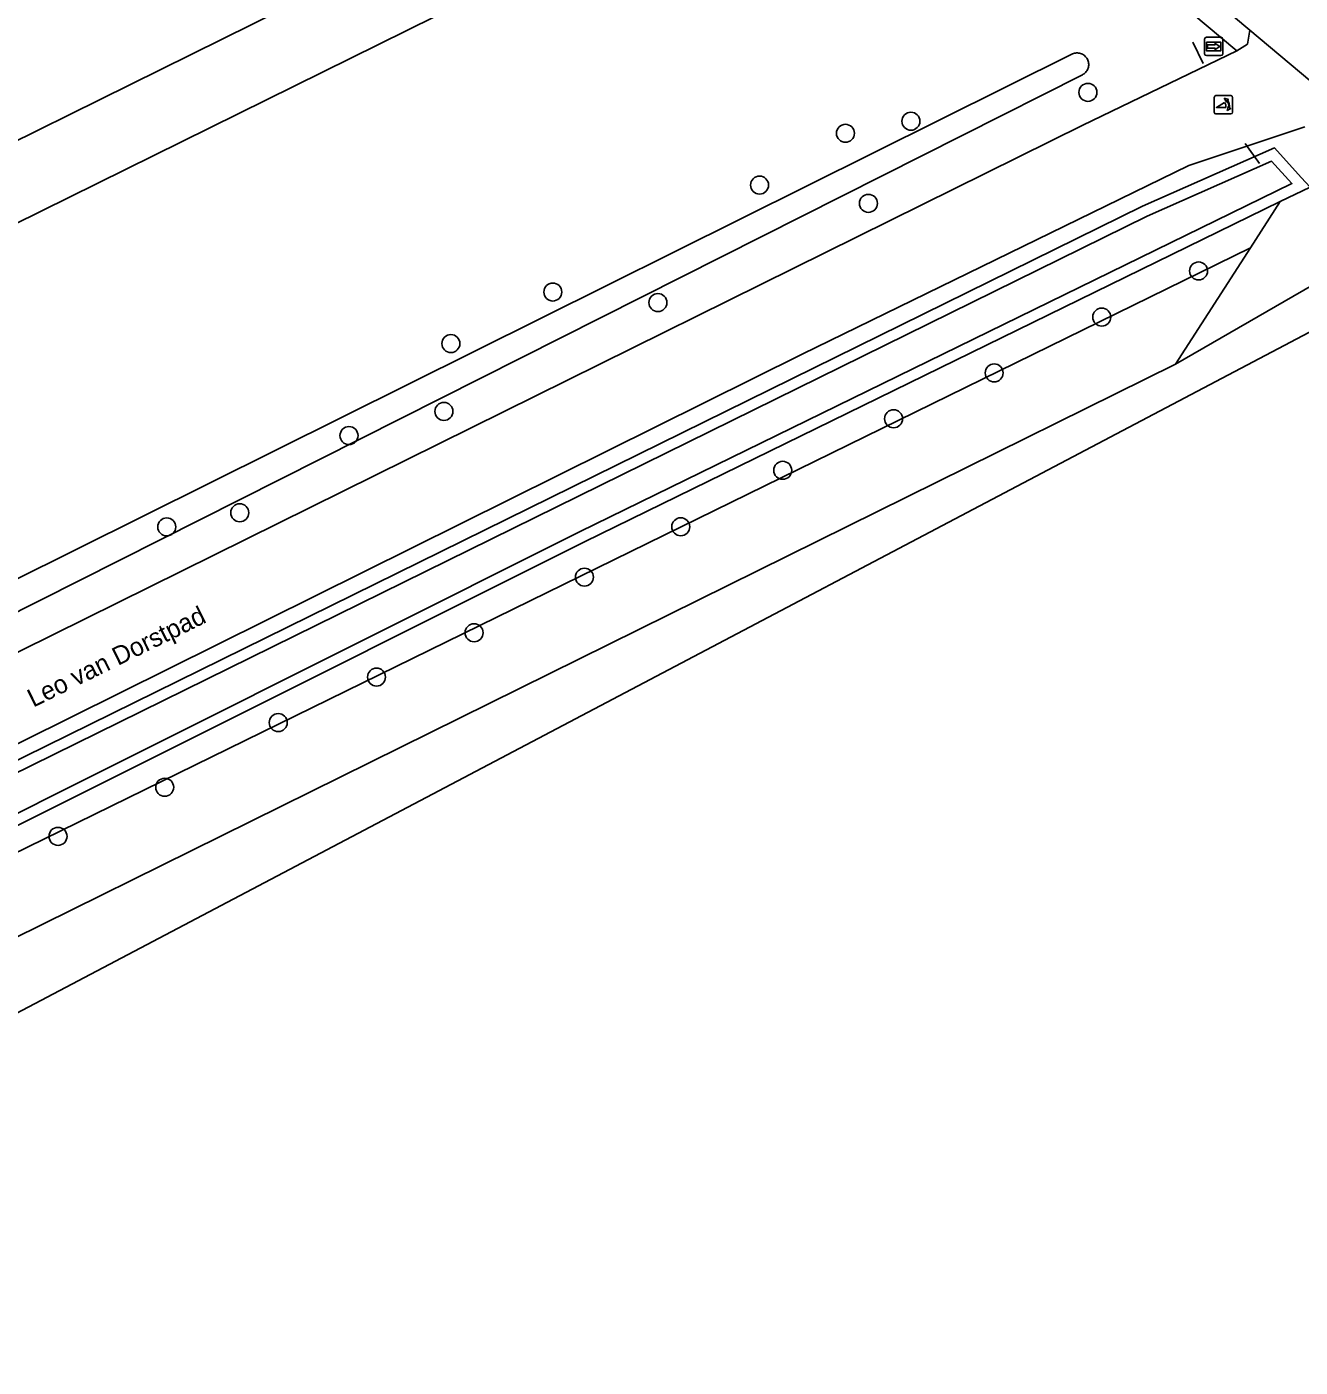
# Model space of a CAD drawing. Extents: x 157321 to 158827, y 386650 to 388532.
# Drawn here: x 158230.9 to 158300.1, y 386849.9 to 386922.7 of the extents above; entities that cross this region are included whole.
import ezdxf

# ---------------------------------------------------------------- set-up
doc = ezdxf.new("R2010")
doc.units = 0
for name, color, linetype in [('IMGEO_Boom', 7, 'Continuous'), ('IMGEO_Fietspad_gesloten', 7, 'Continuous'), ('IMGEO_Grasland_overig', 7, 'Continuous'), ('IMGEO_Groenvoorziening', 7, 'Continuous'), ('IMGEO_Hek', 7, 'Continuous'), ('IMGEO_Openbare_ruimte_label', 7, 'Continuous'), ('IMGEO_Poller', 7, 'Continuous'), ('IMGEO_Voetpad_open', 7, 'Continuous'), ('IMGEO_Waterloop', 7, 'Continuous'), ('IMGEO_Wegwijzer', 7, 'Continuous')]:
    doc.layers.add(name, color=color, linetype=linetype)

msp = doc.modelspace()

# ---------------------------------------------------------------- linework, layer by layer
at = {"layer": 'IMGEO_Boom'}
for centre in [(158288.578, 386919.112), (158278.966, 386917.546), (158275.41, 386916.888), (158270.741, 386914.074), (158276.654, 386913.082), (158294.588, 386909.409), (158259.514, 386908.266), (158265.22, 386907.691), (158289.327, 386906.901), (158253.976, 386905.464), (158283.486, 386903.868), (158253.6, 386901.778), (158278.021, 386901.378), (158248.443, 386900.465), (158272, 386898.579), (158242.51, 386896.275), (158238.542, 386895.506), (158266.464, 386895.51), (158261.23, 386892.774), (158255.237, 386889.752), (158249.937, 386887.346), (158244.599, 386884.876), (158238.432, 386881.358), (158232.638, 386878.693)]:
    msp.add_circle(centre, 0.489, dxfattribs=at)
at = {"layer": 'IMGEO_Fietspad_gesloten'}
for points in [[(158278.393, 386938.472), (158282.172, 386935.247), (158297.373, 386922.485)], [(158296.67, 386921.366), (158297.251, 386921.735), (158297.373, 386922.485)], [(158297.373, 386922.485), (158304.001, 386916.938)], [(158157.22, 386852.456), (158288.293, 386917.324), (158296.67, 386921.366)], [(158300.362, 386917.233), (158294.063, 386915.13), (158273.057, 386904.892), (158206.905, 386872.045), (158161.028, 386849.47)]]:
    msp.add_lwpolyline(points, dxfattribs=at)
at = {"layer": 'IMGEO_Grasland_overig'}
for points in [[(158303.723, 386910.343), (158293.34, 386904.342)], [(158305.326, 386908.574), (158181.714, 386843.44)], [(158178.328, 386847.485), (158293.34, 386904.342)]]:
    msp.add_lwpolyline(points, dxfattribs=at)
at = {"layer": 'IMGEO_Groenvoorziening'}
for points in [[(158143.449, 386873.515), (158167.832, 386885.54), (158167.852, 386885.55), (158190.13, 386896.57), (158190.213, 386896.611), (158274.656, 386938.392), (158275.715, 386938.916)], [(158149.876, 386872.225), (158169.601, 386881.953), (158176.662, 386887.485), (158183.352, 386890.976), (158188.821, 386892.547), (158191.985, 386893.025), (158279.098, 386936.083)], [(158161.727, 386849.006), (158291.549, 386912.934), (158298.705, 386916.096), (158300.167, 386914.49)], [(158300.167, 386914.49), (158300.642, 386913.968), (158299.023, 386913.177)], [(158299.023, 386913.177), (158261.233, 386894.691), (158214.135, 386871.125), (158171.324, 386850.102), (158176.019, 386846.697), (158176.491, 386846.372), (158176.951, 386845.957), (158177.352, 386845.485), (158177.649, 386845.026), (158189.15, 386830.884), (158211.608, 386806.05), (158208.447, 386803.533)], [(158297.408, 386910.666), (158299.023, 386913.177)], [(158297.408, 386910.666), (158175.433, 386850.883), (158178.328, 386847.485)], [(158293.34, 386904.342), (158297.408, 386910.666)]]:
    msp.add_lwpolyline(points, dxfattribs=at)
at = {"layer": 'IMGEO_Hek'}
for points in [[(158294.272, 386921.841), (158294.837, 386920.678)], [(158297.904, 386915.252), (158297.343, 386916.017), (158297.115, 386916.329)]]:
    msp.add_lwpolyline(points, dxfattribs=at)
at = {"layer": 'IMGEO_Poller'}
for p, q in [((158295.438, 386918.839), (158295.438, 386918.032)), ((158295.438, 386918.839), (158295.438, 386918.032)), ((158296.34, 386918.934), (158295.532, 386918.934)), ((158296.34, 386918.934), (158295.532, 386918.934)), ((158296.434, 386918.032), (158296.434, 386918.839)), ((158296.434, 386918.032), (158296.434, 386918.839)), ((158295.532, 386917.937), (158296.34, 386917.937)), ((158295.532, 386917.937), (158296.34, 386917.937))]:
    msp.add_line(p, q, dxfattribs=at)
for points in [[(158296.073, 386918.29), (158295.56, 386918.29), (158295.99, 386918.565)], [(158296.117, 386918.663), (158296.105, 386918.59), (158295.98, 386918.795)], [(158295.98, 386918.795), (158296.211, 386918.729), (158296.14, 386918.697)], [(158296.133, 386918.118), (158296.199, 386918.349), (158296.229, 386918.281)], [(158296.265, 386918.254), (158296.337, 386918.243), (158296.133, 386918.118)]]:
    msp.add_lwpolyline(points, dxfattribs=at)
for centre, radius, start, end in [((158295.532, 386918.839), 0.0946, 90, 180), ((158295.532, 386918.839), 0.0946, 90, 180), ((158295.745, 386918.34), 0.332, 351.32473, 42.4854), ((158295.759, 386918.35), 0.476, 351.75274, 41.16905), ((158295.759, 386918.35), 0.516, 349.35686, 42.29123), ((158296.34, 386918.839), 0.0946, 0, 90), ((158296.34, 386918.839), 0.0946, 0, 90), ((158295.532, 386918.032), 0.0946, 180, 270), ((158295.532, 386918.032), 0.0946, 180, 270), ((158296.34, 386918.032), 0.0946, 270, 0), ((158296.34, 386918.032), 0.0946, 270, 0)]:
    msp.add_arc(centre, radius, start, end, dxfattribs=at)
at = {"layer": 'IMGEO_Voetpad_open'}
msp.add_lwpolyline([(158279.098, 386936.083), (158296.67, 386921.366)], dxfattribs=at)
at = {"layer": 'IMGEO_Waterloop'}
for points in [[(158197.568, 386876.357), (158287.749, 386921.204), (158287.801, 386921.223), (158287.854, 386921.238), (158287.908, 386921.248), (158287.962, 386921.253), (158288.017, 386921.253), (158288.072, 386921.248), (158288.127, 386921.239), (158288.18, 386921.225), (158288.231, 386921.206), (158288.281, 386921.183), (158288.329, 386921.156), (158288.374, 386921.125), (158288.416, 386921.089), (158288.455, 386921.05), (158288.491, 386921.008), (158288.522, 386920.963), (158288.55, 386920.916), (158288.573, 386920.866), (158288.592, 386920.814), (158288.606, 386920.761), (158288.616, 386920.707), (158288.62, 386920.652), (158288.62, 386920.597), (158288.615, 386920.542), (158288.605, 386920.488), (158288.591, 386920.435), (158288.572, 386920.383), (158288.549, 386920.334), (158288.521, 386920.286), (158288.489, 386920.241), (158288.454, 386920.199), (158288.414, 386920.161), (158288.372, 386920.125), (158288.327, 386920.094), (158288.279, 386920.067), (158155.4, 386853.066)], [(158162.308, 386848.619), (158291.804, 386912.387), (158298.551, 386915.368), (158299.654, 386914.157), (158260.965, 386895.232), (158213.867, 386871.666), (158170.158, 386850.202), (158175.671, 386846.204)]]:
    msp.add_lwpolyline(points, dxfattribs=at)
at = {"layer": 'IMGEO_Wegwijzer'}
for p, q in [((158294.911, 386921.206), (158294.911, 386922.006)), ((158294.911, 386922.006), (158294.911, 386921.206)), ((158295.011, 386922.106), (158295.801, 386922.106)), ((158295.801, 386922.106), (158295.011, 386922.106)), ((158295.901, 386922.006), (158295.901, 386921.206)), ((158295.901, 386921.206), (158295.901, 386922.006)), ((158295.801, 386921.106), (158295.011, 386921.106)), ((158295.011, 386921.106), (158295.801, 386921.106))]:
    msp.add_line(p, q, dxfattribs=at)
for points in [[(158295.012, 386921.838), (158295.8, 386921.838), (158295.8, 386921.374), (158295.012, 386921.374), (158295.012, 386921.838)], [(158295.077, 386921.69), (158295.077, 386921.606), (158295.077, 386921.522), (158295.488, 386921.522), (158295.488, 386921.439), (158295.735, 386921.606), (158295.488, 386921.773), (158295.488, 386921.69), (158295.077, 386921.69)]]:
    msp.add_lwpolyline(points, dxfattribs=at)
for centre, start, end in [((158295.011, 386922.006), 90, 180), ((158295.011, 386922.006), 90, 180), ((158295.801, 386922.006), 0, 90), ((158295.801, 386922.006), 360, 90), ((158295.011, 386921.206), 180, 270), ((158295.011, 386921.206), 180, 270), ((158295.801, 386921.206), 270, 0), ((158295.801, 386921.206), 270, 0)]:
    msp.add_arc(centre, 0.1, start, end, dxfattribs=at)

# ---------------------------------------------------------------- texts
at = {"layer": 'IMGEO_Openbare_ruimte_label'}
msp.add_text('Leo van Dorstpad', height=1, rotation=26.23194, dxfattribs=at).set_placement((158231.293, 386885.679))

doc.saveas('drawing.dxf')
